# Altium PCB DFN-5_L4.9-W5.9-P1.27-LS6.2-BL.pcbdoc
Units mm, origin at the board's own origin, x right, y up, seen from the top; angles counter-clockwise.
Board outline 18.83 x 19.32 mm, 2 copper layers (Top Layer, Bottom Layer), stack 0 mm thick; 1 components, 0 nets, 5 pads, 0 vias.
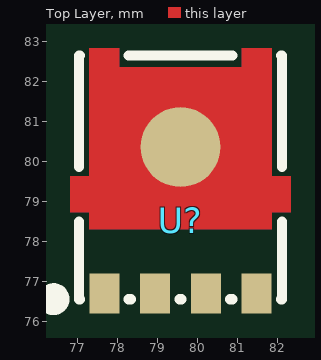
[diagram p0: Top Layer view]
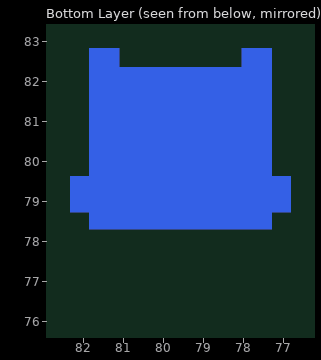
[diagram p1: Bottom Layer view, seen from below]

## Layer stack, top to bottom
Top Layer: signal copper (thickness not stored)
Bottom Layer: signal copper (thickness not stored)

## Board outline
88.68,69.85 69.85,69.85 69.85,89.174 88.68,89.174

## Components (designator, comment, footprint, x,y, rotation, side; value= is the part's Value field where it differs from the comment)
U? "" DFN-5_L4.9-W5.9-P1.27-LS6.2-BL 79.575,78.511 r0 top

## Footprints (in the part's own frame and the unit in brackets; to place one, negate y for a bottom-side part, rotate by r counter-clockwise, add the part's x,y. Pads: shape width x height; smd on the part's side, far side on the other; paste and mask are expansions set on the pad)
DFN-5_L4.9-W5.9-P1.27-LS6.2-BL [mm]
  rect 0.75x1 smd: 1(-1.905,-1.811) 2(-0.635,-1.811) 3(0.635,-1.811) 4(1.905,-1.811)
  round 1.996 smd: 5(0,1.842)
  Top Layer region: -2.28,4.313 -2.28,1.113 -2.755,1.113 -2.755,0.208 -2.28,0.208 -2.28,-0.217 2.28,-0.217 2.28,0.208 2.755,0.208 2.755,1.113 2.28,1.113 2.28,4.313 1.53,4.313 1.53,3.838 -1.53,3.838 -1.53,4.313
  Bottom Layer region: -2.28,4.313 -2.28,1.113 -2.755,1.113 -2.755,0.208 -2.28,0.208 -2.28,-0.217 2.28,-0.217 2.28,0.208 2.755,0.208 2.755,1.113 2.28,1.113 2.28,4.313 1.53,4.313 1.53,3.838 -1.53,3.838 -1.53,4.313
  Multi-Layer region: -2.28,4.313 -2.28,1.113 -2.755,1.113 -2.755,0.208 -2.28,0.208 -2.28,-0.217 2.28,-0.217 2.28,0.208 2.755,0.208 2.755,1.113 2.28,1.113 2.28,4.313 1.53,4.313 1.53,3.838 -1.53,3.838 -1.53,4.313
  silkscreen extent -3.37,-2.16 2.54,4.14

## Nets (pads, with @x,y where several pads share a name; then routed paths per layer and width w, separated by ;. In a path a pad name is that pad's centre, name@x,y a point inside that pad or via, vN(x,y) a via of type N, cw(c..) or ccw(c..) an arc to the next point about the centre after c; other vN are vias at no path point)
pads on no net: U?.1 U?.2 U?.3 U?.4 U?.5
